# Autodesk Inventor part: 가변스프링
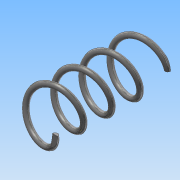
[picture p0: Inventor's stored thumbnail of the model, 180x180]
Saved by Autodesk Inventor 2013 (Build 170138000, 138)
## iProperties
Created: 2015-09
Part Number: 가변스프링
Material: 강철, 탄소
Document SubType Name: Modeling
Designer: Administrator
Density: 7.87 g/cm^3
Mass: 4.92088 g
Surface Area: 12.7468 cm^2
Volume: 0.625271 cm^3
Author: Administrator
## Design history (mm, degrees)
sketch "스케치1"
  geometry: L1 (0, 0)-(0, 42); L2 (0, 0)-(8, 0); L3 (0, 42)-(8, 42); C1 r 1 at (8, 0)
  constraints: 6 end point, 1 centre point, 1 coincident, 1 parallel, 1 perpendicular, 1 vertical
  dimensions: "d0" = 42 distance of L1.start L1.end (derived); "d2" = 16 diameter of L2.end L1; "d3" = 16 diameter of L3.end L1; "d4" = 2 diameter of C1
feature "코일1" sketch "스케치1" pitch "d5" = 10; turns "d7" = 4; dims "d6" = 42 (= d0), "d8" = 0, angle "d9" = 90 deg, angle "d10" = 90 deg, "d11" = 0, "d12" = 0
sketch "스케치2"
  geometry: L1 (42, 10)-(0, 10); L2 (0, 10)-(0, -10); L3 (0, -10)-(42, -10); L4 (42, -10)-(42, 10); 2 further points
  constraints: 8 end point, 2 parallel, 1 coincident, 1 horizontal, 1 midpoint, 1 perpendicular
  dimensions: "d13" = 42 distance of L2.end L3.end (derived); "d15" = 20 distance of L1.end L2.end
extrude "돌출1" sketch "스케치2" stored distance "d16" = 10; taper "d17" = 0 deg
node "솔리드1"
